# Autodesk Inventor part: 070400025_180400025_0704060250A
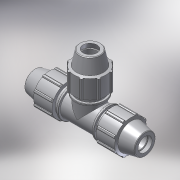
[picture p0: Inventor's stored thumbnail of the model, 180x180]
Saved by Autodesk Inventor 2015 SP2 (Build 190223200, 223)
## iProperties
Created: 2017-02
Part Number: 070400025_180400025_0704060250A
Material: PVC-Piping
Description: PLASSON TEE 25-25-25
Document SubType Name: Modeling
Designer: KIM
Mass: 92.6774 g
Surface Area: 199.44 cm^2
Volume: 66.1981 cm^3
Density: 1.4 g/cm^3
Appearance: Smooth - White
Author: KIM
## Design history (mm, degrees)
derived "07040.ipt"
feature "Solid1::07040.ipt"
tag "TaggingFeature1"
body "Solid1"
other parameters: "d2" = 25, "d4" = 6.5, "d5" = 19.5, "d7" = 54, "d11" = 2.6, "d13" = 120 deg, "d14" = 37.5, "d15" = 12 deg, "d16" = 46.98, "d18" = 1.25, "d19" = 35 deg, "d20" = 17.5 deg, "d21" = 50.22, "d23" = 0, "d25" = 360 deg, "d27" = 1.08, "d33" = 0.5, "d42" = 27.3, "d43" = 1.62, "d46" = 0.75, "d63" = 58, "d67" = 40.5, "d76" = 25, "d77" = 54, "d78" = 12 deg, "d79" = 78, "d80" = 120 deg, "d81" = 37.5, "d82" = 6.5, "d85" = 40.5, "d86" = 46.98, "d87" = 2.6, "d88" = 2.6, "d89" = 19.5, "d90" = 27.3, "d96" = 5.2, "d98" = 50.22, "d99" = 35 deg, "d100" = 17.5 deg, "d102" = 0, "d103" = 1.08, "d107" = 360 deg, "d109" = 0.75, "d112" = 1.25, "d118" = 360 deg, "d121" = 0, "d128" = 156, "d131" = 22.5, "d132" = 22.5, "d133" = 58, "d134" = 1.16, "d135" = 5.2, "d152" = 0, "d154" = 0, "d156" = 0, "d158" = 0, "d_" = 25, "E_" = 54, "A_" = 78, "l_" = 58, "H_" = 156
